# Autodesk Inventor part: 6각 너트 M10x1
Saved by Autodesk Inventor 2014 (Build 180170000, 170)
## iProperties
Created: 2026-06
Part Number: 6각 너트 M10x1
Material: 일반
Document SubType Name: Modeling
Designer: dg
Density: 1 g/cm^3
Appearance: 기본값
Author: dg
Author: jhkim
Description: 6각 너트 및 6각 가는 너트
Creation Date: 2026-05-29
Sending System: Autodesk Inventor 2027
Preprocessor: ST-DEVELOPER v20.1
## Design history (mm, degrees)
node "6각 너트 M10x11"
body "Solid1"
node "기준1"
